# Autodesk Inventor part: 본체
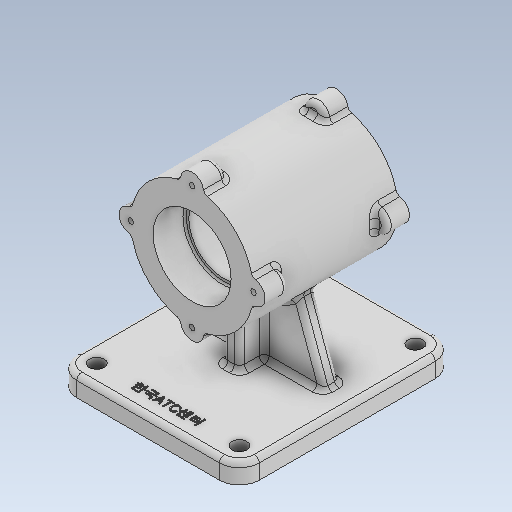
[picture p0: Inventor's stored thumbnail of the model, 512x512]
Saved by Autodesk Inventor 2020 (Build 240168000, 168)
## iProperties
Created: 2022-11
Part Number: 본체
Material: 일반
Document SubType Name: Modeling
Designer: owner
Density: 1 g/cm^3
Appearance: 기본값
Mass: 450.176 g
Surface Area: 800.088 cm^2
Volume: 450.176 cm^3
Author: owner
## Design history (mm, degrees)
sketch "스케치1"
  geometry: C1 r 37 at (0, 0); 1 further point
  constraints: 1 centre point, 1 coincident
  dimensions: "d0" = 74 diameter of C1
extrude "돌출1" new body sketch "스케치1" distance "d1" = 87; taper "d2" = 0 deg
sketch "스케치2"
  geometry: C1 r 23.5 at (0, 0); 1 further point
  constraints: 1 centre point, 1 coincident
  dimensions: "d3" = 47 diameter of C1
extrude "돌출2" cut sketch "스케치2" distance "d4" = 19; taper "d5" = 0 deg
sketch "스케치3"
  geometry: C1 r 23.5 at (0, 0); 1 further point
  constraints: 1 centre point, 1 coincident
  dimensions: "d6" = 47 diameter of C1
extrude "돌출3" cut sketch "스케치3" distance "d7" = 19; taper "d8" = 0 deg
sketch "스케치4"
  geometry: C1 r 21 at (0, 0); 1 further point
  constraints: 1 centre point, 1 coincident
  dimensions: "d9" = 42 diameter of C1
extrude "돌출4" cut sketch "스케치4" stored distance "d10" = 19; taper "d11" = 0 deg
sketch "스케치5"
  geometry: C1 r 37 at (0, 0) reference; C2 r 7 at (0, 37); 3 further points
  constraints: 1 centre point, 1 vertical alignment
  dimensions: "d12" = 14 diameter of C2; "d13" = 37 distance of point (0, 0) C2.centre
extrude "돌출5" join sketch "스케치5" distance "d14" = 14; taper "d15" = 0 deg
sketch "스케치6"
  geometry: A1 r 7 centre (0, 37) between (6.969, 36.338) and (-6.969, 36.338) reference; 2 further points
  constraints: 1 coincident
hole "구멍1" sketch "스케치6" at (0, 37) diameter "d16" = 3.242; stored, may be unused: countersink angle "d20" = 90 deg, drill point angle "d22" = 118 deg; dims "d17" = 8, "d18" = 4, "d19" = 2, "d21" = 11.8
sketch "스케치7"
  geometry: A1 r 7 centre (37, 0) between (36.338, -6.969) and (36.338, 6.969) reference; A2 r 37 centre (0, 0) between (36.338, -6.969) and (36.338, 6.969) reference; 1 further point
extrude "돌출6" join sketch "스케치7" distance "d26" = 14; taper "d27" = 0 deg
sketch "스케치8"
  geometry: A1 r 7 centre (37, 0) between (36.338, -6.969) and (36.338, 6.969) reference; 2 further points
  constraints: 1 coincident
hole "구멍2" sketch "스케치8" at (37, 0) diameter "d28" = 3.242; stored, may be unused: countersink angle "d32" = 90 deg, drill point angle "d34" = 118 deg; dims "d29" = 8, "d30" = 4, "d31" = 2, "d33" = 11.8
node "작업 평면2"
sketch "스케치9"
  geometry: L1 (55, 26.5)-(-55, 26.5); L2 (-55, 26.5)-(-55, -103.5); L3 (-55, -103.5)-(55, -103.5); L4 (55, -103.5)-(55, 26.5); 2 further points
  constraints: 8 end point, 2 parallel, 1 horizontal, 1 perpendicular, 1 vertical alignment
  dimensions: "d39" = 110 distance of L3.end L2.end; "d40" = 130 distance of L2.end L1.end; "d41" = 43.5 distance of point (0, -43.5) point (0, 0); "d42" = 70 distance from line of point (0, -43.5) L1; "d43" = 55 distance from line of point (0, 0) L4
extrude "돌출7" join sketch "스케치9" distance "d44" = 12; taper "d45" = 0 deg
node "작업 평면4"
sketch "스케치10"
  geometry: L1 (55, -70)-(-55, -70) reference; L2 (-55, -70)-(55, -70) reference; L3 (-41, -70)-(-25.336, -26.964); L4 (25.336, -26.964)-(41, -70); A1 r 37 centre (0, 0) between (-36.338, -6.969) and (-6.969, -36.338) reference; A2 r 37 centre (0, 0) between (6.969, -36.338) and (36.338, -6.969) reference; A3 r 37 centre (0, 0) between (-6.969, -36.338) and (6.969, -36.338) reference; A4 r 37 centre (0, 0) between (-36.338, -6.969) and (-6.969, -36.338) reference; A5 r 37 centre (0, 0) between (6.969, -36.338) and (36.338, -6.969) reference; 5 further points
  constraints: 4 end point, 2 point on circle, 2 point on line
  dimensions: "d47" = 110 deg angle of L3 L1; "d48" = 110 deg angle of L1 L4; "d49" = 14 distance of L3.start L1.end; "d50" = 14 distance of L1.start L4.end
extrude "돌출8" join sketch "스케치10" stored distance "d51" = 10; taper "d52" = 0 deg
sketch "스케치11"
  geometry: L1 (-37, -14)-(-37, -73) reference; L2 (-37, -23.5)-(-70, -23.5); L3 (-26.964, -38.5)-(-70, -38.5) reference; 1 further point
  constraints: 2 end point, 1 horizontal, 1 point on line
  dimensions: "d53" = 15 distance between parallel lines of L3 L2
feature "리브1" sketch "스케치11" dims "d54" = 1, "d55" = 10, "d56" = 0, "d57" = 0, "d58" = 1, "d59" = 1
sketch "스케치12"
  geometry: L1 (-37, -14)-(-37, -73) reference; L2 (-37, -63.5)-(-70.015, -63.5); L3 (-70, -48.5)-(-26.964, -48.5) reference; 1 further point
  constraints: 2 end point, 1 perpendicular, 1 point on line
  dimensions: "d60" = 15 distance between parallel lines of L2 L3
feature "리브2" sketch "스케치12" dims "d61" = 1, "d62" = 10, "d63" = 0, "d64" = 0, "d65" = 1, "d66" = 1
fillet "모깎기1" dims "d67" = 12
sketch "스케치13"
  geometry: L1 (-43, -26.5)-(43, -26.5) reference; L2 (55, -14.5)-(55, 91.5) reference; L3 (-55, 91.5)-(-55, -14.5) reference; L4 (43, 103.5)-(-43, 103.5) reference; 5 further points
  dimensions: "d71" = 12 distance from line of point (43, -14.5) L1; "d72" = 12 distance from line of L2 point (43, -14.5); "d73" = 12 distance from line of point (-43, -14.5) L1; "d74" = 12 distance from line of point (-43, -14.5) L3; "d75" = 12 distance from line of point (-43, 91.5) L3; "d76" = 12 distance from line of point (-43, 91.5) L4; "d77" = 12 distance from line of L2 point (43, 91.5); "d78" = 12 distance from line of point (43, 91.5) L4
hole "구멍3" sketch "스케치13" at (43, -14.5), (43, 91.5), (-43, 91.5), (-43, -14.5) diameter "d79" = 9; stored, may be unused: countersink angle "d83" = 90 deg, drill point angle "d85" = 0 deg; dims "d80" = 8, "d81" = 4, "d82" = 2, "d84" = 12
sketch "스케치14"
  geometry: L1 (-43, -26.5)-(43, -26.5) reference; L2 (-7, 0)-(7, 0) reference; 5 further points
  constraints: 1 midpoint, 1 vertical alignment, 1 other
  dimensions: "d86" = 12 distance from line of L1 point (0, -14.5)
feature "엠보싱1" sketch "스케치14" dims "d87" = 0.5, "d88" = 0
fillet "모깎기2" dims "d89" = 1
fillet "모깎기3" dims "d90" = 3
fillet "모깎기4" dims "d91" = 3
fillet "모깎기5" dims "d92" = 3
fillet "모깎기6" dims "d93" = 3
fillet "모깎기7" dims "d94" = 3
node "솔리드1"
pattern_circular "원형 패턴1" dims angle "d24" = 360 deg
pattern_circular "원형 패턴2" dims angle "d36" = 360 deg
feature "A9D066F2-1C7D-4E18-AEED-F7BC21143FA4" dims "d79" = 9, "d80" = 8, "d81" = 4, "d82" = 2, "d83" = 90 deg, "d84" = 12, "d85" = 0
other parameters: "d38" = -82, "d46" = -43.5
